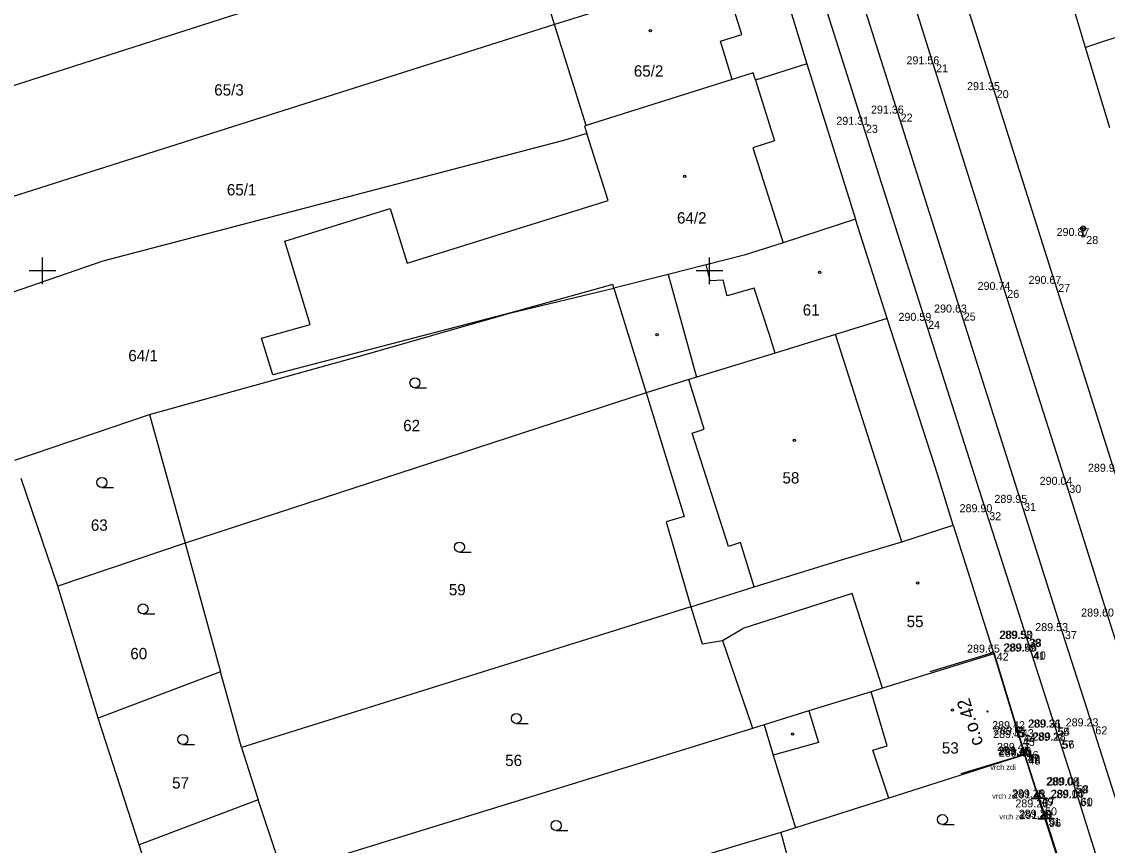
# Model space of a CAD drawing. Extents: x -599970 to -599524, y -1154772 to -1154457.
# Drawn here: x -599751.5 to -599670.2, y -1154593 to -1154531.3 of the extents above; entities that cross this region are included whole.
import ezdxf

# ---------------------------------------------------------------- set-up
doc = ezdxf.new("R2010")
doc.units = 0
for name, color, linetype in [('Z-BUDOVY', 7, 'Continuous'), ('Z-ELEKTRICKE SKRINE LAMPY', 7, 'Continuous'), ('Z-KATASTRALNI MAPA', 7, 'Continuous'), ('Z-KRIZKY CTVERCOVE SITE', 7, 'Continuous'), ('Z-ORIENTACNI A POPISNA CISLA', 7, 'Continuous'), ('Z-PLOT BETONOVY', 7, 'Continuous'), ('Z-PODROBNE BODY', 7, 'Continuous'), ('Z-PODROBNE BODY-CISLO', 7, 'Continuous'), ('Z-PODROBNE BODY-VYSKA', 7, 'Continuous'), ('Z-SCHODY', 7, 'Continuous'), ('Z-VODOROVNE ZNACENI', 7, 'Continuous'), ('Z-VSTUPY VJEZDY', 7, 'Continuous'), ('Z-VYSKOVE BODY', 7, 'Continuous'), ('Z-ZPEVNENE PLOCHY', 7, 'Continuous')]:
    doc.layers.add(name, color=color, linetype=linetype)

msp = doc.modelspace()

# ---------------------------------------------------------------- linework, layer by layer
at = {"layer": 'Z-BUDOVY'}
for p, q in [((-599678.7, -1154578.61), (-599683.48, -1154580.06)), ((-599676.38, -1154586.25), (-599681.16, -1154587.7))]:
    msp.add_line(p, q, dxfattribs=at)
msp.add_lwpolyline([(-599678.7, -1154578.61), (-599676.38, -1154586.25)], dxfattribs=at)
at = {"layer": 'Z-ELEKTRICKE SKRINE LAMPY'}
for p, q in [((-599672.122, -1154546.959), (-599671.858, -1154546.695)), ((-599671.854, -1154546.958), (-599672.118, -1154546.693)), ((-599671.99, -1154547.29), (-599671.99, -1154547.015))]:
    msp.add_line(p, q, dxfattribs=at)
for points in [[(-599677.07, -1154584.475), (-599676.57, -1154584.475), (-599676.57, -1154584.225), (-599677.07, -1154584.225)], [(-599676.93, -1154584.865), (-599676.43, -1154584.865), (-599676.43, -1154584.615), (-599676.93, -1154584.615)]]:
    msp.add_lwpolyline(points, close=True, dxfattribs=at)
for centre, radius in [((-599671.99, -1154546.828), 0.188), ((-599671.99, -1154547.39), 0.1)]:
    msp.add_circle(centre, radius, dxfattribs=at)
at = {"layer": 'Z-KATASTRALNI MAPA'}
for p, q in [((-599714.03, -1154523.9), (-599760.21, -1154538.7)), ((-599711.61, -1154531.55), (-599714.03, -1154523.9)), ((-599671.83, -1154533.26), (-599673.97, -1154526.16)), ((-599695.22, -1154526.32), (-599692.71, -1154534.5)), ((-599697.57, -1154532.3), (-599699.05, -1154527.62)), ((-599711.61, -1154531.55), (-599757.79, -1154546.22)), ((-599709.25, -1154539.12), (-599711.61, -1154531.55)), ((-599699.19, -1154532.79), (-599697.57, -1154532.3)), ((-599698.31, -1154535.67), (-599699.19, -1154532.79)), ((-599670.01, -1154539.29), (-599671.83, -1154533.26)), ((-599692.71, -1154534.5), (-599696.56, -1154535.72)), ((-599692.71, -1154534.5), (-599689.07, -1154546.14)), ((-599696.56, -1154535.72), (-599695.12, -1154540.26)), ((-599695.12, -1154540.26), (-599696.75, -1154540.78)), ((-599696.75, -1154540.78), (-599694.49, -1154547.9)), ((-599686.68, -1154553.57), (-599689.07, -1154546.14)), ((-599699.96, -1154550.74), (-599700.26, -1154549.55)), ((-599703.11, -1154550.27), (-599700.99, -1154557.98)), ((-599707.26, -1154551.02), (-599714.88, -1154553.16)), ((-599714.88, -1154553.16), (-599707.18, -1154551.3)), ((-599707.18, -1154551.3), (-599707.26, -1154551.02)), ((-599707.18, -1154551.3), (-599704.76, -1154559.14)), ((-599698.98, -1154550.71), (-599699.96, -1154550.74)), ((-599698.69, -1154551.87), (-599698.98, -1154550.71)), ((-599696.66, -1154551.3), (-599698.69, -1154551.87)), ((-599695.5, -1154554.8), (-599696.66, -1154551.3)), ((-599682.92, -1154565.25), (-599686.68, -1154553.57)), ((-599695.07, -1154556.16), (-599695.5, -1154554.8)), ((-599685.59, -1154570.3), (-599690.56, -1154554.77)), ((-599722.076, -1154558.77), (-599721.201, -1154558.77)), ((-599700.41, -1154561.87), (-599701.54, -1154558.15)), ((-599704.76, -1154559.14), (-599739.29, -1154570.4)), ((-599752.06, -1154564.2), (-599741.96, -1154560.76)), ((-599741.96, -1154560.76), (-599739.29, -1154570.4)), ((-599701.29, -1154562.16), (-599700.41, -1154561.87)), ((-599698.58, -1154570.65), (-599701.29, -1154562.16)), ((-599681.75, -1154569.06), (-599682.92, -1154565.25)), ((-599748.83, -1154573.64), (-599751.59, -1154565.56)), ((-599745.537, -1154566.24), (-599744.662, -1154566.24)), ((-599681.75, -1154569.06), (-599678.7, -1154578.71)), ((-599739.29, -1154570.4), (-599748.83, -1154573.64)), ((-599739.29, -1154570.4), (-599736.65, -1154580.06)), ((-599697.67, -1154570.35), (-599698.58, -1154570.65)), ((-599696.65, -1154573.69), (-599697.67, -1154570.35)), ((-599718.747, -1154571.08), (-599717.872, -1154571.08)), ((-599745.81, -1154583.53), (-599748.83, -1154573.64)), ((-599689.31, -1154574.18), (-599697.5, -1154576.8)), ((-599687.04, -1154581.28), (-599689.31, -1154574.18)), ((-599742.456, -1154575.71), (-599741.581, -1154575.71)), ((-599701.39, -1154575.17), (-599735.08, -1154585.73)), ((-599699.02, -1154577.7), (-599697.5, -1154576.8)), ((-599678.7, -1154578.71), (-599676.4, -1154586.26)), ((-599736.65, -1154580.06), (-599745.81, -1154583.53)), ((-599735.08, -1154585.73), (-599736.65, -1154580.06)), ((-599686.7, -1154585.59), (-599687.88, -1154581.54)), ((-599692.56, -1154582.98), (-599691.84, -1154585.34)), ((-599742.74, -1154593.02), (-599745.81, -1154583.53)), ((-599714.476, -1154583.92), (-599713.601, -1154583.92)), ((-599696.79, -1154584.29), (-599731.99, -1154595.15)), ((-599695.91, -1154584.02), (-599696.79, -1154584.29)), ((-599739.466, -1154585.5), (-599738.591, -1154585.5)), ((-599691.84, -1154585.34), (-599695.22, -1154586.3)), ((-599687.76, -1154585.92), (-599686.7, -1154585.59)), ((-599735.08, -1154585.73), (-599733.83, -1154589.64)), ((-599686.56, -1154589.51), (-599687.76, -1154585.92)), ((-599676.4, -1154586.26), (-599673.37, -1154595.74)), ((-599733.83, -1154589.64), (-599742.74, -1154593.02)), ((-599731.99, -1154595.15), (-599733.83, -1154589.64)), ((-599694.67, -1154592.08), (-599720.86, -1154599.93)), ((-599711.497, -1154591.94), (-599710.622, -1154591.94)), ((-599693.57, -1154591.75), (-599694.67, -1154592.08)), ((-599694.67, -1154592.08), (-599693.47, -1154596.46)), ((-599682.547, -1154591.5), (-599681.672, -1154591.5)), ((-599741.29, -1154597.51), (-599742.74, -1154593.02))]:
    msp.add_line(p, q, dxfattribs=at)
for points in [[(-599695.22, -1154526.32), (-599699.05, -1154527.62), (-599700.66, -1154528.12), (-599711.61, -1154531.55)], [(-599652, -1154526.95), (-599652.86, -1154526.99), (-599661.78, -1154529.94), (-599671.83, -1154533.26)], [(-599696.56, -1154535.72), (-599696.74, -1154535.17), (-599698.31, -1154535.67), (-599709.25, -1154539.12)], [(-599709.25, -1154539.12), (-599709.37, -1154539.16), (-599709.19, -1154539.72)], [(-599709.19, -1154539.72), (-599710.84, -1154540.22), (-599745.47, -1154549.29), (-599755.69, -1154552.79)], [(-599714.88, -1154553.16), (-599732.72, -1154557.8), (-599733.57, -1154555.04), (-599729.92, -1154554.02), (-599731.84, -1154547.79), (-599723.93, -1154545.34), (-599722.65, -1154549.43), (-599707.6, -1154544.72), (-599709.19, -1154539.72)], [(-599689.07, -1154546.14), (-599694.49, -1154547.9), (-599697.4, -1154548.83), (-599700.26, -1154549.55), (-599703.11, -1154550.27), (-599707.18, -1154551.3)], [(-599741.96, -1154560.76), (-599726.4, -1154556.44), (-599714.88, -1154553.16)], [(-599686.68, -1154553.57), (-599690.56, -1154554.77), (-599695.07, -1154556.16), (-599700.99, -1154557.98), (-599701.54, -1154558.15), (-599704.76, -1154559.14)], [(-599704.76, -1154559.14), (-599701.91, -1154568.4), (-599703.26, -1154568.8), (-599701.39, -1154575.17)], [(-599701.39, -1154575.17), (-599696.65, -1154573.69), (-599690.11, -1154571.66), (-599685.59, -1154570.3), (-599681.75, -1154569.06)], [(-599701.39, -1154575.17), (-599700.56, -1154577.96), (-599699.02, -1154577.7), (-599696.86, -1154584.04), (-599696.79, -1154584.29)], [(-599678.7, -1154578.71), (-599687.04, -1154581.28), (-599687.88, -1154581.54), (-599692.56, -1154582.98), (-599695.91, -1154584.02)], [(-599695.91, -1154584.02), (-599695.22, -1154586.3), (-599693.57, -1154591.75)], [(-599676.4, -1154586.26), (-599686.56, -1154589.51), (-599693.57, -1154591.75)]]:
    msp.add_lwpolyline(points, dxfattribs=at)
for centre, radius in [((-599704.433, -1154532), 0.0875), ((-599701.873, -1154542.91), 0.0875), ((-599691.753, -1154550.12), 0.0875), ((-599703.933, -1154554.79), 0.0875), ((-599722.076, -1154558.395), 0.375), ((-599693.653, -1154562.7), 0.0875), ((-599745.536, -1154565.865), 0.375), ((-599718.746, -1154570.705), 0.375), ((-599684.403, -1154573.4), 0.0875), ((-599742.456, -1154575.335), 0.375), ((-599714.476, -1154583.545), 0.375), ((-599681.793, -1154582.91), 0.0875), ((-599739.466, -1154585.125), 0.375), ((-599693.783, -1154584.7), 0.0875), ((-599711.496, -1154591.565), 0.375), ((-599682.546, -1154591.125), 0.375)]:
    msp.add_circle(centre, radius, dxfattribs=at)
at = {"layer": 'Z-KRIZKY CTVERCOVE SITE'}
for p, q in [((-599750, -1154551), (-599750, -1154549)), ((-599700, -1154551), (-599700, -1154549)), ((-599749, -1154550), (-599751, -1154550)), ((-599699, -1154550), (-599701, -1154550))]:
    msp.add_line(p, q, dxfattribs=at)
at = {"layer": 'Z-PLOT BETONOVY'}
for points in [[(-599676.38, -1154586.25), (-599676.32, -1154586.41)], [(-599675.34, -1154589.46), (-599675.08, -1154590.21)], [(-599673.31, -1154595.75), (-599674.83, -1154590.98)]]:
    msp.add_lwpolyline(points, dxfattribs=at)
at = {"layer": 'Z-PODROBNE BODY'}
for p, q in [((-599683.24, -1154534.53), (-599683.24, -1154534.53)), ((-599678.7, -1154536.46), (-599678.7, -1154536.46)), ((-599685.9, -1154538.22), (-599685.9, -1154538.22)), ((-599688.5, -1154539.06), (-599688.5, -1154539.06)), ((-599671.99, -1154547.39), (-599671.99, -1154547.39)), ((-599677.91, -1154551.43), (-599677.91, -1154551.43)), ((-599674.09, -1154550.98), (-599674.09, -1154550.98)), ((-599683.84, -1154553.75), (-599683.84, -1154553.75)), ((-599681.17, -1154553.13), (-599681.17, -1154553.13)), ((-599673.26, -1154566.04), (-599673.26, -1154566.04)), ((-599676.65, -1154567.39), (-599676.65, -1154567.39)), ((-599679.26, -1154568.09), (-599679.26, -1154568.09)), ((-599673.59, -1154577), (-599673.59, -1154577)), ((-599676.29, -1154577.58), (-599676.29, -1154577.58)), ((-599676.23, -1154577.57), (-599676.23, -1154577.57)), ((-599678.7, -1154578.61), (-599678.7, -1154578.61)), ((-599675.98, -1154578.54), (-599675.98, -1154578.54)), ((-599675.92, -1154578.52), (-599675.92, -1154578.52)), ((-599676.82, -1154584.35), (-599676.82, -1154584.35)), ((-599676.68, -1154584.74), (-599676.68, -1154584.74)), ((-599674.15, -1154584.24), (-599674.15, -1154584.24)), ((-599674.1, -1154584.22), (-599674.1, -1154584.22)), ((-599671.31, -1154584.14), (-599671.31, -1154584.14)), ((-599676.75, -1154585.01), (-599676.75, -1154585.01)), ((-599673.83, -1154585.22), (-599673.83, -1154585.22)), ((-599673.77, -1154585.19), (-599673.77, -1154585.19)), ((-599676.46, -1154585.98), (-599676.46, -1154585.98)), ((-599676.38, -1154586.25), (-599676.38, -1154586.25)), ((-599676.33, -1154586.29), (-599676.33, -1154586.29)), ((-599676.32, -1154586.41), (-599676.32, -1154586.41)), ((-599672.78, -1154588.57), (-599672.78, -1154588.57)), ((-599672.7, -1154588.55), (-599672.7, -1154588.55)), ((-599675.34, -1154589.46), (-599675.34, -1154589.46)), ((-599675.28, -1154589.54), (-599675.28, -1154589.54)), ((-599672.45, -1154589.52), (-599672.45, -1154589.52)), ((-599672.4, -1154589.48), (-599672.4, -1154589.48)), ((-599675.08, -1154590.21), (-599675.08, -1154590.21)), ((-599674.83, -1154590.98), (-599674.83, -1154590.98)), ((-599674.77, -1154591.08), (-599674.77, -1154591.08))]:
    msp.add_line(p, q, dxfattribs=at)
at = {"layer": 'Z-SCHODY'}
msp.add_circle((-599679.17, -1154583.03), 0.0438, dxfattribs=at)
at = {"layer": 'Z-VODOROVNE ZNACENI'}
for points in [[(-599694.02, -1154499.99), (-599689.54, -1154514.32), (-599685.46, -1154527.42), (-599683.24, -1154534.53), (-599677.91, -1154551.43), (-599673.26, -1154566.04), (-599670.15, -1154575.91), (-599664.69, -1154593.08), (-599661.63, -1154602.65), (-599657.71, -1154615.01), (-599654.33, -1154625.58), (-599650.3, -1154638.13), (-599646.03, -1154651.51), (-599641.58, -1154665.41), (-599629.85, -1154702.06), (-599625.38, -1154716.06)], [(-599697.63, -1154501.15), (-599693.46, -1154514.34), (-599689.12, -1154528.02), (-599685.9, -1154538.22), (-599681.17, -1154553.13), (-599676.65, -1154567.39), (-599673.59, -1154577), (-599671.31, -1154584.14), (-599668.11, -1154594.2), (-599666.34, -1154599.75), (-599661.15, -1154616.02), (-599657.79, -1154626.57), (-599653.82, -1154639.02), (-599649.52, -1154652.61), (-599645.03, -1154666.6), (-599639.28, -1154684.62), (-599637.35, -1154690.63), (-599633.4, -1154703.39)]]:
    msp.add_lwpolyline(points, dxfattribs=at)
at = {"layer": 'Z-VSTUPY VJEZDY'}
for points in [[(-599676.75, -1154585.01), (-599676.46, -1154585.98)], [(-599676.32, -1154586.41), (-599675.34, -1154589.46)], [(-599675.08, -1154590.21), (-599674.83, -1154590.98)]]:
    msp.add_lwpolyline(points, dxfattribs=at)
at = {"layer": 'Z-VYSKOVE BODY'}
for p, q in [((-599675.705, -1154586.29), (-599676.955, -1154586.29)), ((-599676.955, -1154586.29), (-599676.33, -1154586.29)), ((-599676.33, -1154585.665), (-599676.33, -1154585.915)), ((-599676.33, -1154585.915), (-599676.33, -1154585.665)), ((-599676.33, -1154586.29), (-599676.33, -1154585.665)), ((-599676.33, -1154585.665), (-599676.33, -1154585.915)), ((-599675.705, -1154586.29), (-599676.33, -1154586.29)), ((-599674.655, -1154589.54), (-599675.905, -1154589.54)), ((-599675.905, -1154589.54), (-599675.28, -1154589.54)), ((-599675.28, -1154588.915), (-599675.28, -1154589.165)), ((-599675.28, -1154589.165), (-599675.28, -1154588.915)), ((-599675.28, -1154589.54), (-599675.28, -1154588.915)), ((-599675.28, -1154588.915), (-599675.28, -1154589.165)), ((-599674.655, -1154589.54), (-599675.28, -1154589.54)), ((-599674.77, -1154590.455), (-599674.77, -1154590.705)), ((-599674.77, -1154590.705), (-599674.77, -1154590.455)), ((-599674.77, -1154591.08), (-599674.77, -1154590.455)), ((-599674.77, -1154590.455), (-599674.77, -1154590.705)), ((-599674.145, -1154591.08), (-599675.395, -1154591.08)), ((-599675.395, -1154591.08), (-599674.77, -1154591.08)), ((-599674.145, -1154591.08), (-599674.77, -1154591.08))]:
    msp.add_line(p, q, dxfattribs=at)
for centre, start, end in [((-599676.33, -1154586.29), 89.99999, 179.99999), ((-599676.33, -1154586.29), 0, 89.99999), ((-599675.28, -1154589.54), 89.99999, 179.99999), ((-599675.28, -1154589.54), 0, 89.99999), ((-599674.77, -1154591.08), 89.99999, 179.99999), ((-599674.77, -1154591.08), 0, 89.99999)]:
    msp.add_arc(centre, 0.375, start, end, dxfattribs=at)
at = {"layer": 'Z-ZPEVNENE PLOCHY'}
for points in [[(-599687.9, -1154498.79), (-599683.81, -1154511.87), (-599681.17, -1154520.27), (-599680.7, -1154530), (-599680.59, -1154530.5), (-599678.7, -1154536.46), (-599674.09, -1154550.98), (-599669.64, -1154565.06), (-599666.53, -1154574.78), (-599664.2, -1154582.16), (-599662.32, -1154587.97), (-599661.17, -1154588.61), (-599661.03, -1154589.1), (-599661.9, -1154589.37), (-599661.11, -1154591.93), (-599657.79, -1154602.2), (-599654.15, -1154613.66), (-599652.29, -1154619.52), (-599651.12, -1154620.18), (-599650.97, -1154620.63), (-599651.85, -1154620.91), (-599651.44, -1154622.26)], [(-599700.18, -1154501.85), (-599696.19, -1154514.6), (-599691.72, -1154528.96), (-599688.5, -1154539.06), (-599683.84, -1154553.75), (-599679.26, -1154568.09), (-599676.23, -1154577.57), (-599675.92, -1154578.52), (-599674.1, -1154584.22), (-599673.77, -1154585.19), (-599672.7, -1154588.55), (-599672.4, -1154589.48), (-599670.73, -1154594.81)]]:
    msp.add_lwpolyline(points, dxfattribs=at)

# ---------------------------------------------------------------- texts
at = {"layer": 'Z-KATASTRALNI MAPA'}
for s, p in [('65/2', (-599705.672, -1154535.45)), ('65/3', (-599737.119, -1154536.87)), ('65/1', (-599736.171, -1154544.35)), ('64/2', (-599702.439, -1154546.46)), ('61', (-599693.018, -1154553.36)), ('64/1', (-599743.558, -1154556.78)), ('62', (-599722.959, -1154562.02)), ('58', (-599694.536, -1154565.94)), ('63', (-599746.366, -1154569.48)), ('59', (-599719.536, -1154574.32)), ('55', (-599685.229, -1154576.7)), ('60', (-599743.406, -1154579.11)), ('53', (-599682.589, -1154586.18)), ('56', (-599715.316, -1154587.11)), ('57', (-599740.276, -1154588.8))]:
    msp.add_text(s, height=0.85, dxfattribs=at).set_placement(p)
at = {"layer": 'Z-ORIENTACNI A POPISNA CISLA'}
msp.add_text('c.o.42', height=1, rotation=106.8917, dxfattribs=at).set_placement((-599679.48, -1154585.44))
at = {"layer": 'Z-PODROBNE BODY-CISLO'}
for s, p in [(' 21', (-599683.24, -1154535.13)), (' 20', (-599678.7, -1154537.06)), (' 22', (-599685.9, -1154538.82)), (' 23', (-599688.5, -1154539.66)), (' 28', (-599671.99, -1154547.99)), (' 26', (-599677.91, -1154552.03)), (' 27', (-599674.09, -1154551.58)), (' 24', (-599683.84, -1154554.35)), (' 25', (-599681.17, -1154553.73)), (' 30', (-599673.26, -1154566.64)), (' 31', (-599676.65, -1154567.99)), (' 32', (-599679.26, -1154568.69)), (' 37', (-599673.59, -1154577.6)), (' 39', (-599676.29, -1154578.18)), (' 38', (-599676.23, -1154578.17)), (' 42', (-599678.7, -1154579.21)), (' 41', (-599675.98, -1154579.14)), (' 40', (-599675.92, -1154579.12)), (' 43', (-599676.82, -1154584.95)), (' 44', (-599676.68, -1154585.34)), (' 55', (-599674.15, -1154584.84)), (' 54', (-599674.1, -1154584.82)), (' 62', (-599671.31, -1154584.74)), (' 45', (-599676.75, -1154585.61)), (' 57', (-599673.83, -1154585.82)), (' 56', (-599673.77, -1154585.79)), (' 46', (-599676.46, -1154586.58)), (' 47', (-599676.38, -1154586.85)), (' 48', (-599676.32, -1154587.01)), (' 98', (-599676.33, -1154586.89)), (' 59', (-599672.78, -1154589.17)), (' 58', (-599672.7, -1154589.15)), (' 49', (-599675.34, -1154590.06)), (' 97', (-599675.28, -1154590.14)), (' 61', (-599672.45, -1154590.12)), (' 60', (-599672.4, -1154590.08)), (' 50', (-599675.08, -1154590.81)), (' 51', (-599674.83, -1154591.58)), (' 96', (-599674.77, -1154591.68))]:
    msp.add_text(s, height=0.6, dxfattribs=at).set_placement(p)
at = {"layer": 'Z-PODROBNE BODY-VYSKA'}
for s, p in [('291.56 ', (-599685.24, -1154534.53)), ('291.35 ', (-599680.7, -1154536.46)), ('291.36 ', (-599687.9, -1154538.22)), ('291.31 ', (-599690.5, -1154539.06)), ('290.87 ', (-599673.99, -1154547.39)), ('290.67 ', (-599676.09, -1154550.98)), ('290.74 ', (-599679.91, -1154551.43)), ('290.63 ', (-599683.17, -1154553.13)), ('290.59 ', (-599685.84, -1154553.75)), ('289.99 ', (-599671.64, -1154565.06)), ('290.04 ', (-599675.26, -1154566.04)), ('289.95 ', (-599678.65, -1154567.39)), ('289.90 ', (-599681.26, -1154568.09)), ('289.60 ', (-599672.15, -1154575.91)), ('289.53 ', (-599675.59, -1154577)), ('289.53 ', (-599678.29, -1154577.58)), ('289.50 ', (-599678.23, -1154577.57)), ('289.65 ', (-599680.7, -1154578.61)), ('289.59 ', (-599677.98, -1154578.54)), ('289.46 ', (-599677.92, -1154578.52)), ('289.42 ', (-599678.82, -1154584.35)), ('289.36 ', (-599676.15, -1154584.24)), ('289.21 ', (-599676.1, -1154584.22)), ('289.23 ', (-599673.31, -1154584.14)), ('289.47 ', (-599678.75, -1154585.01)), ('289.41 ', (-599678.68, -1154584.74)), ('289.21 ', (-599675.83, -1154585.22)), ('289.18 ', (-599675.77, -1154585.19)), ('289.47 ', (-599678.46, -1154585.98)), ('289.41 ', (-599678.38, -1154586.25)), ('291.46 ', (-599678.33, -1154586.29)), ('289.40 ', (-599678.32, -1154586.41)), ('289.08 ', (-599674.78, -1154588.57)), ('289.04 ', (-599674.7, -1154588.55)), ('289.26 ', (-599677.34, -1154589.46)), ('289.00 ', (-599674.4, -1154589.48)), ('291.43 ', (-599677.28, -1154589.54)), ('289.26 ', (-599677.08, -1154590.21)), ('289.14 ', (-599674.45, -1154589.52)), ('289.20 ', (-599676.83, -1154590.98)), ('291.30 ', (-599676.77, -1154591.08))]:
    msp.add_text(s, height=0.6, dxfattribs=at).set_placement(p)
at = {"layer": 'Z-VYSKOVE BODY'}
for p in [(-599678.96, -1154587.4), (-599678.82, -1154589.56), (-599678.28, -1154591.11)]:
    msp.add_text('vrch zdi', height=0.4, dxfattribs=at).set_placement(p)

doc.saveas('drawing.dxf')
